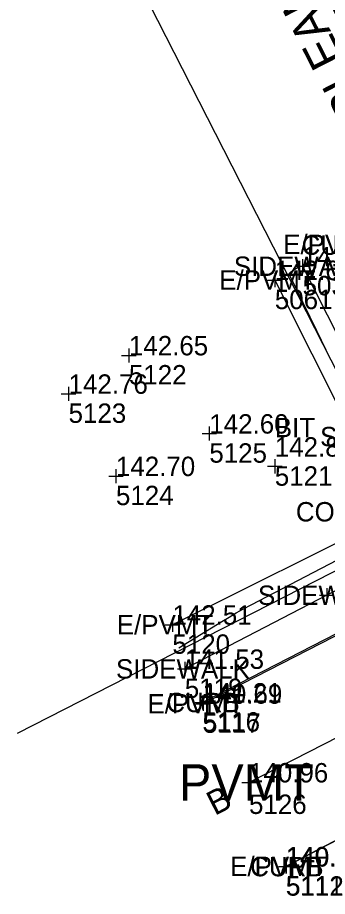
# Model space of a CAD drawing. Extents: x 13482495 to 13483389, y 311646 to 312209.
# Drawn here: x 13482545.4 to 13482596.6, y 311718.3 to 311863.4 of the extents above; entities that cross this region are included whole.
import ezdxf

# ---------------------------------------------------------------- set-up
doc = ezdxf.new("R2010")
doc.units = 0
for name, color, linetype in [('V-ANNO-TEXT', 7, 'Continuous'), ('V-PROP-RWAY', 7, 'Continuous'), ('V-PVMT-CNTR', 7, 'Continuous'), ('V-PVMT-ROAD', 7, 'Continuous'), ('V-PVMT-SPOT', 7, 'Continuous'), ('V-SITE-IDEN', 7, 'Continuous'), ('V-SITE-SPOT', 7, 'Continuous'), ('V-SITE-WALK', 7, 'Continuous'), ('V-SURV-DATA', 7, 'Continuous'), ('V-SURV-PNTS', 7, 'Continuous'), ('V-TOPO-LINE-IDEN', 7, 'Continuous'), ('V-TOPO-MINR', 7, 'Continuous'), ('V-TOPO-SPOT', 7, 'Continuous')]:
    doc.layers.add(name, color=color, linetype=linetype)

msp = doc.modelspace()

# ---------------------------------------------------------------- linework, layer by layer
at = {"layer": 'V-PROP-RWAY'}
for p, q in [((13482611.43, 311778.98), (13482567.23, 311865.61)), ((13482545.45, 311745.31), (13482611.43, 311778.98))]:
    msp.add_line(p, q, dxfattribs=at)
at = {"layer": 'V-PVMT-CNTR'}
msp.add_lwpolyline([(13482583.66, 311737.16), (13482615.84, 311753.6), (13482631.76, 311761.33), (13482644.15, 311768.11), (13482660.2, 311776.18), (13482708.88, 311801.22), (13482756.86, 311825.71), (13482802.86, 311849.14), (13482850.91, 311873.11), (13482897.46, 311897.25), (13482945.27, 311921.45), (13482988.06, 311943.31), (13483031.89, 311965.62), (13483078.61, 311989.65), (13483123.69, 312012.73), (13483173.43, 312038.09), (13483222.97, 312063.09), (13483269.03, 312086.57), (13483297.77, 312101.09)], dxfattribs=at)
at = {"layer": 'V-PVMT-ROAD'}
for points in [[(13482598.3, 311825.83), (13482613.09, 311797.25), (13482617.22, 311788.99), (13482618.84, 311785.9), (13482620.2, 311783.17), (13482620.85, 311781.63), (13482621.07, 311780.89), (13482621.28, 311779.78), (13482621.28, 311778.11), (13482620.93, 311776.51), (13482620.66, 311775.81), (13482619.95, 311774.49), (13482619.29, 311773.59), (13482618.43, 311772.71), (13482616.46, 311771.23), (13482613.95, 311769.69), (13482612.64, 311769.01), (13482608.21, 311766.9), (13482575.96, 311750.35)], [(13482598.49, 311825.96), (13482613.21, 311797.28), (13482619.01, 311786.01), (13482620.39, 311783.26), (13482621.03, 311781.73), (13482621.25, 311780.98), (13482621.45, 311779.86), (13482621.44, 311778.18), (13482621.06, 311776.5), (13482620.63, 311775.42), (13482619.85, 311774.06), (13482619.39, 311773.43), (13482618.58, 311772.54), (13482617.99, 311772), (13482616.71, 311771.06), (13482615.41, 311770.29), (13482612.68, 311768.91), (13482576.07, 311750.15)], [(13482587.93, 311820.07), (13482606.26, 311783.6), (13482606.65, 311780.86), (13482571.01, 311763.19)], [(13482659.84, 311704.83), (13482645.17, 311734.1), (13482642.05, 311740.02), (13482641.56, 311740.84), (13482640.35, 311742.28), (13482638.71, 311743.59), (13482637.79, 311744.13), (13482635.83, 311744.92), (13482634.82, 311745.16), (13482633.31, 311745.24), (13482631.96, 311745.01), (13482631.08, 311744.71), (13482629.27, 311743.86), (13482589.73, 311723.31)], [(13482645.08, 311734.06), (13482641.94, 311740.06), (13482641.46, 311740.84), (13482640.29, 311742.2), (13482639.5, 311742.86), (13482637.73, 311743.93), (13482635.81, 311744.67), (13482634.82, 311744.9), (13482633.33, 311745), (13482631.98, 311744.83), (13482631.09, 311744.57), (13482629.3, 311743.79), (13482589.79, 311723.27)]]:
    msp.add_lwpolyline(points, dxfattribs=at)
at = {"layer": 'V-PVMT-SPOT'}
for p, q in [((13482592.51, 311823.51), (13482592.51, 311821.19)), ((13482591.31, 311822.35), (13482593.71, 311822.35)), ((13482586.73, 311820.07), (13482589.13, 311820.07)), ((13482587.93, 311821.23), (13482587.93, 311818.91)), ((13482596.49, 311769.21), (13482596.49, 311766.89)), ((13482595.29, 311768.05), (13482597.69, 311768.05)), ((13482571.01, 311764.35), (13482571.01, 311762.03)), ((13482569.81, 311763.19), (13482572.21, 311763.19)), ((13482573.06, 311757.06), (13482573.06, 311754.74)), ((13482571.86, 311755.9), (13482574.26, 311755.9)), ((13482574.76, 311750.35), (13482577.16, 311750.35)), ((13482575.96, 311751.51), (13482575.96, 311749.19)), ((13482576.07, 311751.31), (13482576.07, 311748.99)), ((13482574.87, 311750.15), (13482577.27, 311750.15)), ((13482583.66, 311738.32), (13482583.66, 311736)), ((13482582.46, 311737.16), (13482584.86, 311737.16)), ((13482589.73, 311724.47), (13482589.73, 311722.15)), ((13482589.79, 311724.43), (13482589.79, 311722.11)), ((13482588.53, 311723.31), (13482590.93, 311723.31)), ((13482588.59, 311723.27), (13482590.99, 311723.27))]:
    msp.add_line(p, q, dxfattribs=at)
at = {"layer": 'V-SITE-SPOT'}
for p, q in [((13482587.92, 311790.49), (13482587.92, 311788.17)), ((13482586.72, 311789.33), (13482589.12, 311789.33))]:
    msp.add_line(p, q, dxfattribs=at)
at = {"layer": 'V-SITE-WALK'}
msp.add_lwpolyline([(13482592.51, 311822.35), (13482606.75, 311794.23), (13482612.62, 311782.76), (13482615.1, 311777.43), (13482609.2, 311774.43), (13482596.49, 311768.05), (13482573.06, 311755.9)], dxfattribs=at)
at = {"layer": 'V-TOPO-MINR'}
for points in [[(13482597.16, 311806.9), (13482596.38, 311808.49), (13482595.61, 311810.08), (13482594.84, 311811.67), (13482590.41, 311820.84), (13482590.36, 311821.02), (13482590.36, 311821.18), (13482590.44, 311821.33), (13482590.58, 311821.45), (13482591.65, 311822.15)], [(13482572.08, 311759.38), (13482579.17, 311763.74), (13482580.36, 311764.46), (13482581.56, 311765.15), (13482582.77, 311765.83), (13482584, 311766.48), (13482602.05, 311775.89)]]:
    msp.add_lwpolyline(points, dxfattribs=at)
at = {"layer": 'V-TOPO-SPOT'}
for p, q in [((13482563.83, 311808.8), (13482563.83, 311806.48)), ((13482562.63, 311807.64), (13482565.03, 311807.64)), ((13482552.67, 311801.3), (13482555.07, 311801.3)), ((13482553.87, 311802.46), (13482553.87, 311800.14)), ((13482577.11, 311795.89), (13482577.11, 311793.57)), ((13482575.91, 311794.73), (13482578.31, 311794.73)), ((13482561.69, 311788.88), (13482561.69, 311786.56)), ((13482560.49, 311787.72), (13482562.89, 311787.72))]:
    msp.add_line(p, q, dxfattribs=at)

# ---------------------------------------------------------------- texts
msp.add_text('B', height=4, rotation=27.0313).set_placement((13482578, 311731.61))
at = {"layer": 'V-ANNO-TEXT'}
for s, p in [('ORLEANS ST. ', (13482606.48, 311842.96)), ('50 FT WD)', (13482611.14, 311850.23))]:
    msp.add_text(s, height=5.6, rotation=117.0313, dxfattribs=at).set_placement(p)
at = {"layer": 'V-PVMT-SPOT'}
for s, p in [('141.38', (13482592.51, 311822.35)), ('142.63', (13482587.93, 311820.07)), ('142.51', (13482571.01, 311763.19)), ('141.53', (13482573.06, 311755.9)), ('141.21', (13482575.96, 311750.35)), ('140.69', (13482576.07, 311750.15)), ('140.96', (13482583.66, 311737.16)), ('140.63', (13482589.73, 311723.31)), ('140.70', (13482589.79, 311723.27))]:
    msp.add_text(s, height=3.2, dxfattribs=at).set_placement(p)
at = {"layer": 'V-SITE-IDEN'}
msp.add_text('BIT', height=3.2, dxfattribs=at).set_placement((13482587.92, 311794.13))
at = {"layer": 'V-SITE-SPOT'}
msp.add_text('142.82', height=3.2, dxfattribs=at).set_placement((13482587.92, 311790.93))
at = {"layer": 'V-SURV-DATA'}
msp.add_text('COMP ELEV 144.20', height=3.2, dxfattribs=at).set_placement((13482591.4, 311780.23))
at = {"layer": 'V-SURV-PNTS'}
for s, p in [('5039', (13482592.51, 311817.55)), ('5061', (13482587.93, 311815.27)), ('5122', (13482563.83, 311802.84)), ('5123', (13482553.87, 311796.5)), ('5125', (13482577.11, 311789.93)), ('5121', (13482587.92, 311786.13)), ('5124', (13482561.69, 311782.92)), ('5120', (13482571.01, 311758.39)), ('5119', (13482573.06, 311751.1)), ('5116', (13482575.96, 311745.55)), ('5117', (13482576.07, 311745.35)), ('5126', (13482583.66, 311731.96)), ('5111', (13482589.73, 311718.51)), ('5112', (13482589.79, 311718.47))]:
    msp.add_text(s, height=3.2, dxfattribs=at).set_placement(p)
at = {"layer": 'V-TOPO-LINE-IDEN'}
for s, height, p in [('E/PVMT', 3.2, (13482589.31, 311824.36)), ('CURB', 3.2, (13482592.35, 311824.23)), ('SIDEWALK', 3.2, (13482581.16, 311820.75)), ('E/PVMT', 3.2, (13482578.75, 311818.47)), ('SIDEWALK', 3.2, (13482595.4, 311792.63)), ('SIDEWALK', 3.2, (13482585.14, 311766.45)), ('E/PVMT', 3.2, (13482561.83, 311761.59)), ('SIDEWALK', 3.2, (13482561.7, 311754.3)), ('E/PVMT', 3.2, (13482566.89, 311748.55)), ('CURB', 3.2, (13482570.01, 311748.75)), ('PVMT', 6, (13482572.09, 311734.16)), ('E/PVMT', 3.2, (13482580.55, 311721.71)), ('CURB', 3.2, (13482583.85, 311721.67))]:
    msp.add_text(s, height=height, dxfattribs=at).set_placement(p)
at = {"layer": 'V-TOPO-SPOT'}
for s, p in [('142.65', (13482563.83, 311807.64)), ('142.76', (13482553.87, 311801.3)), ('142.60', (13482577.11, 311794.73)), ('142.70', (13482561.69, 311787.72))]:
    msp.add_text(s, height=3.2, dxfattribs=at).set_placement(p)

doc.saveas('drawing.dxf')
